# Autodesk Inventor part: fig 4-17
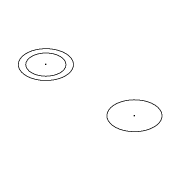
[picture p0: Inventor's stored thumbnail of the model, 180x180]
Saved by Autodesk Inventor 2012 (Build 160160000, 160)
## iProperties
Created: 2005-02
Part Number: fig 4-17
Document SubType Name: Modeling
Designer: CADCIM
Manufacturer: Standard
Standards Organization: Custom
Density: 1 g/cm^3
Material: Default
Author: CADCIM
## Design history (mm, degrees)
sketch "Sketch1"
  geometry: C1 r 7.935 at (-23.563, 7.599); C2 r 7.935 at (12.452, 7.599); C3 r 5.782 at (-23.563, 7.599)
  constraints: 3 centre point, 1 coincident, 1 equal radius, 1 other
